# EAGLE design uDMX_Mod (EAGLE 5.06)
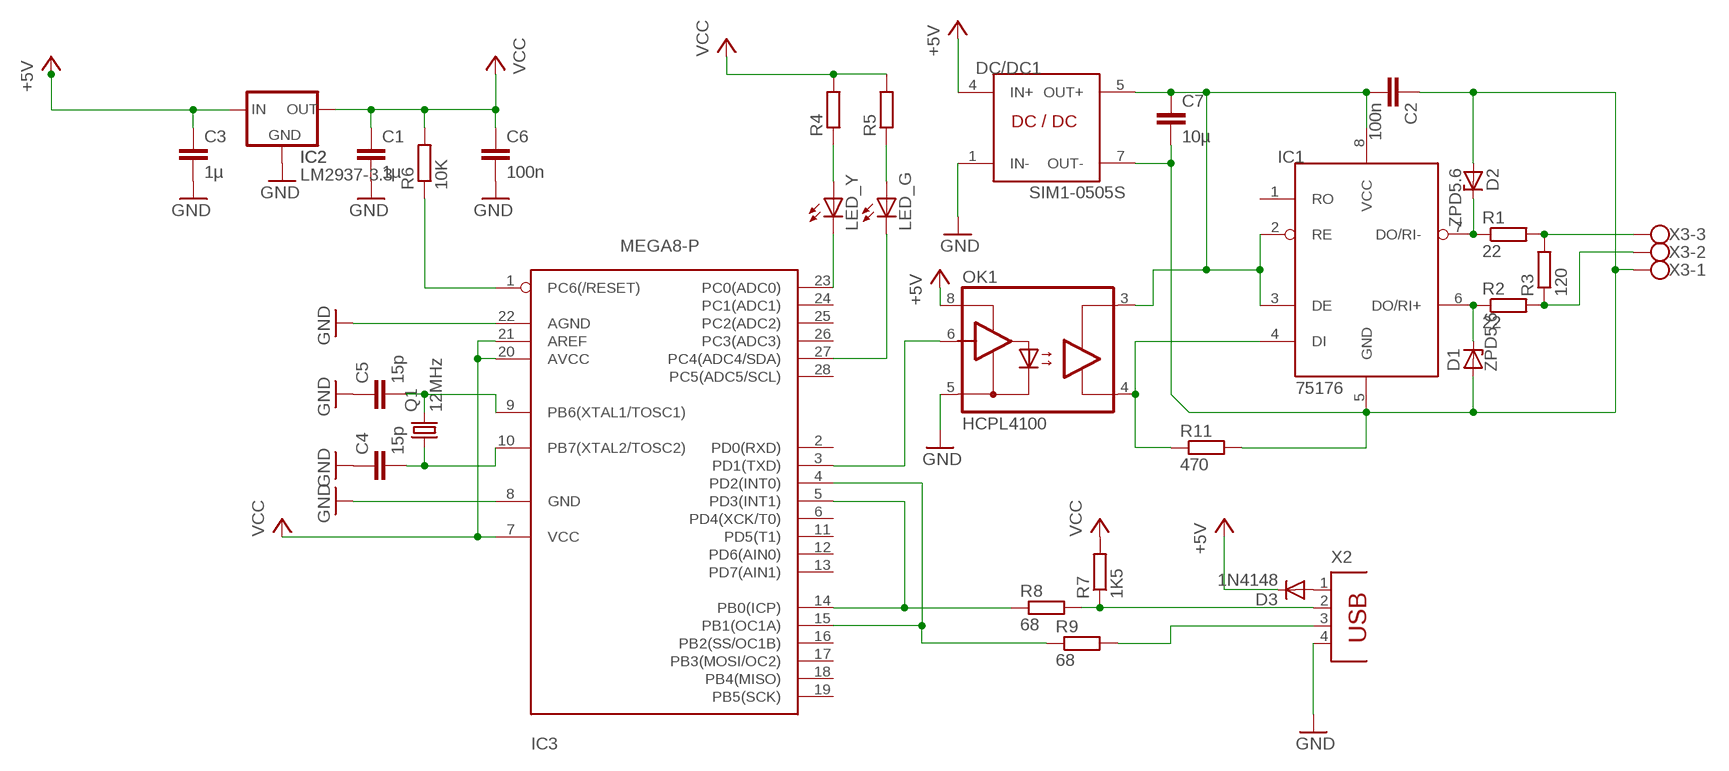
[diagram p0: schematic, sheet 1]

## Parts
C1  1µ  C2.5/4  [C2.5-4]
C2  100n  C2.5/4  [C2.5-4]
C3  1µ  C2.5/4  [C2.5-4]
C4  15p  C2.5/4  [C2.5-4]
C5  15p  C2.5/4  [C2.5-4]
C6  100n  C2.5/4  [C2.5-4]
C7  10µ  C2.5/4  [C2.5-4]
D1  ZPD5.6  ZPD  [DO35Z10]
D2  ZPD5.6  ZPD  [DO35Z10]
D3  1N4148  [DO35-10]
DC/DC1  SIM1-0505S  [DIL08]
IC1  75176  [DIL08]
IC2  LM2937-3.3  LM2937  [TO220S]
IC3  MEGA8-P  [DIL28-3]
LED_G  LED3MM  [LED3MM]
LED_Y  LED3MM  [LED3MM]
OK1  HCPL4100  [DIL08]
Q1  12MHz  CRYSTALHC18U-V  [HC18U-V]
R1  22  R-EU_0204/7  [0204/7]
R2  22  R-EU_0204/7  [0204/7]
R3  120  R-EU_0204/7  [0204/7]
R4  R-EU_0204/7  [0204/7]
R5  R-EU_0204/7  [0204/7]
R6  10K  R-EU_0204/7  [0204/7]
R7  1K5  R-EU_0204/7  [0204/7]
R8  68  R-EU_0204/7  [0204/7]
R9  68  R-EU_0204/7  [0204/7]
R11  470  R-EU_0204/7  [0204/7]
X2  PN61729  [PN61729]
X3  W237-103  [W237-103]

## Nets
+5V: C3.1 D3.C DC/DC1.4(IN+) IC2.1(IN) OK1.8(VDD1)
D-: R7.1 R8.2 X2.2
DMX2: R1.2 R3.2 X3.3
GND: C1.2 C3.2 C4.1 C5.1 C6.2 DC/DC1.1(IN-) IC2.2(GND) IC3.8(GND) IC3.22(AGND) OK1.5(GND1) X2.4
N$1: IC3.5(PD3(INT1)) IC3.14(PB0(ICP)) R8.1
N$3: D2.C IC1.7(DO/RI-) R1.1
N$4: D1.C IC1.6(DO/RI+) R2.1
N$5: IC3.3(PD1(TXD)) OK1.6(VI)
N$6: IC3.4(PD2(INT0)) IC3.15(PB1(OC1A)) R9.1
N$7: LED_Y.A R4.1
N$8: LED_G.A R5.1
N$9: IC3.23(PC0(ADC0)) LED_Y.K(C)
N$10: R9.2 X2.3
N$11: IC3.27(PC4(ADC4/SDA)) LED_G.K(C)
N$12: C2.1 C7.2 D1.A D2.A DC/DC1.7(OUT-) IC1.5(GND) R11.2 X3.1
N$13: R2.2 R3.1 X3.2
N$14: D3.A X2.1
N$15: C2.2 C7.1 DC/DC1.5(OUT+) IC1.2(RE) IC1.3(DE) IC1.8(VCC) OK1.3(I+)
N$17: IC1.4(DI) OK1.4(I-) R11.1
N$37: C4.2 IC3.10(PB7(XTAL2/TOSC2)) Q1.1
N$38: C5.2 IC3.9(PB6(XTAL1/TOSC1)) Q1.2
N$47: IC3.1(PC6(/RESET)) R6.1
VCC: C1.1 C6.1 IC2.3(OUT) IC3.7(VCC) IC3.20(AVCC) IC3.21(AREF) R4.2 R5.2 R6.2 R7.2
Unconnected: IC1.1(RO) IC3.2(PD0(RXD)) IC3.6(PD4(XCK/T0)) IC3.11(PD5(T1)) IC3.12(PD6(AIN0)) IC3.13(PD7(AIN1)) IC3.16(PB2(SS/OC1B)) IC3.17(PB3(MOSI/OC2)) IC3.18(PB4(MISO)) IC3.19(PB5(SCK)) IC3.24(PC1(ADC1)) IC3.25(PC2(ADC2)) IC3.26(PC3(ADC3)) IC3.28(PC5(ADC5/SCL))

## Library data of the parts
C1-C7 = capacitor-wima:C: CAPACITOR
D1 D2 = diode:ZPD: Z DIODE
D3 = diode:1N4148: DIODE
DC/DC1 = Lutz:SIM1-0505S
IC1 = Lutz:75176
IC2 = Lutz:LM2937: VOLTAGE REGULATOR
IC3 = atmel:MEGA8-P: MICROCONTROLLER 8 Kbytes FLASH 1 kbytes SRAM 512 bytes EEPROM USART 4-channel 10 bit ADC 2-channel 8 bit ADC Source: avr.lbr
LED_G LED_Y = led:LED: LED
OK1 = Lutz:HCPL4100: HEWLETT PACKARD OPTO COUPLER
Q1 = crystal:CRYSTAL: CRYSTAL
R1-R9 R11 = rcl:R-EU_: RESISTOR, European symbol
X2 = con-berg:PN61729: BERG USB connector
X3 = con-wago-500:W237-103: WAGO SCREW CLAMP

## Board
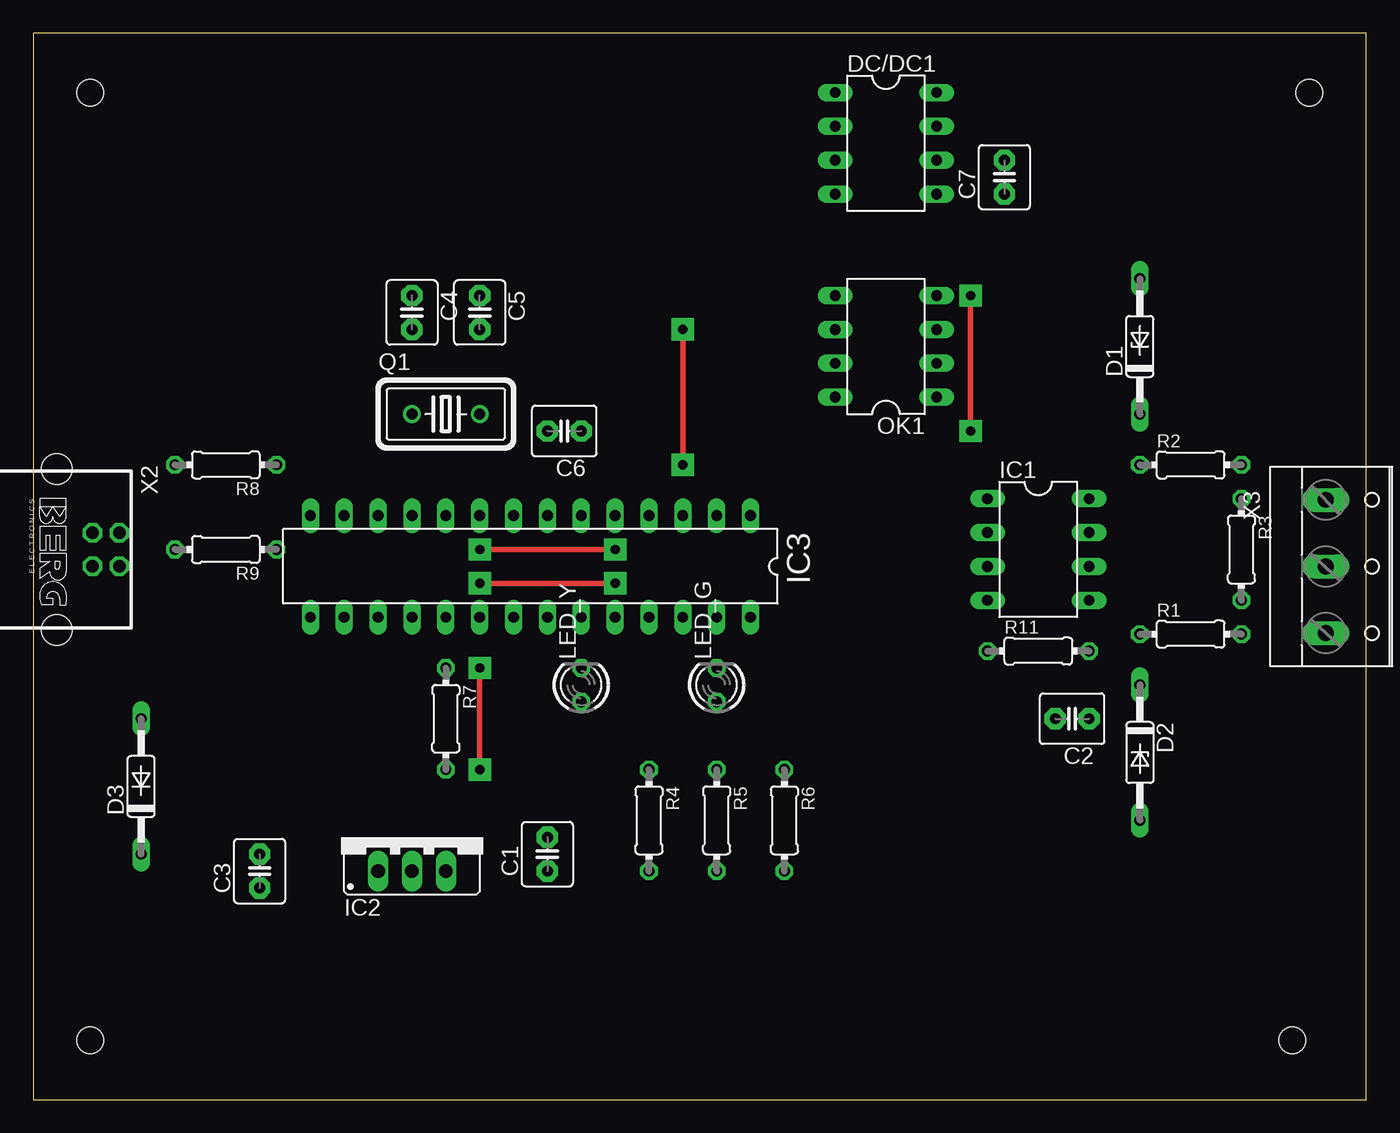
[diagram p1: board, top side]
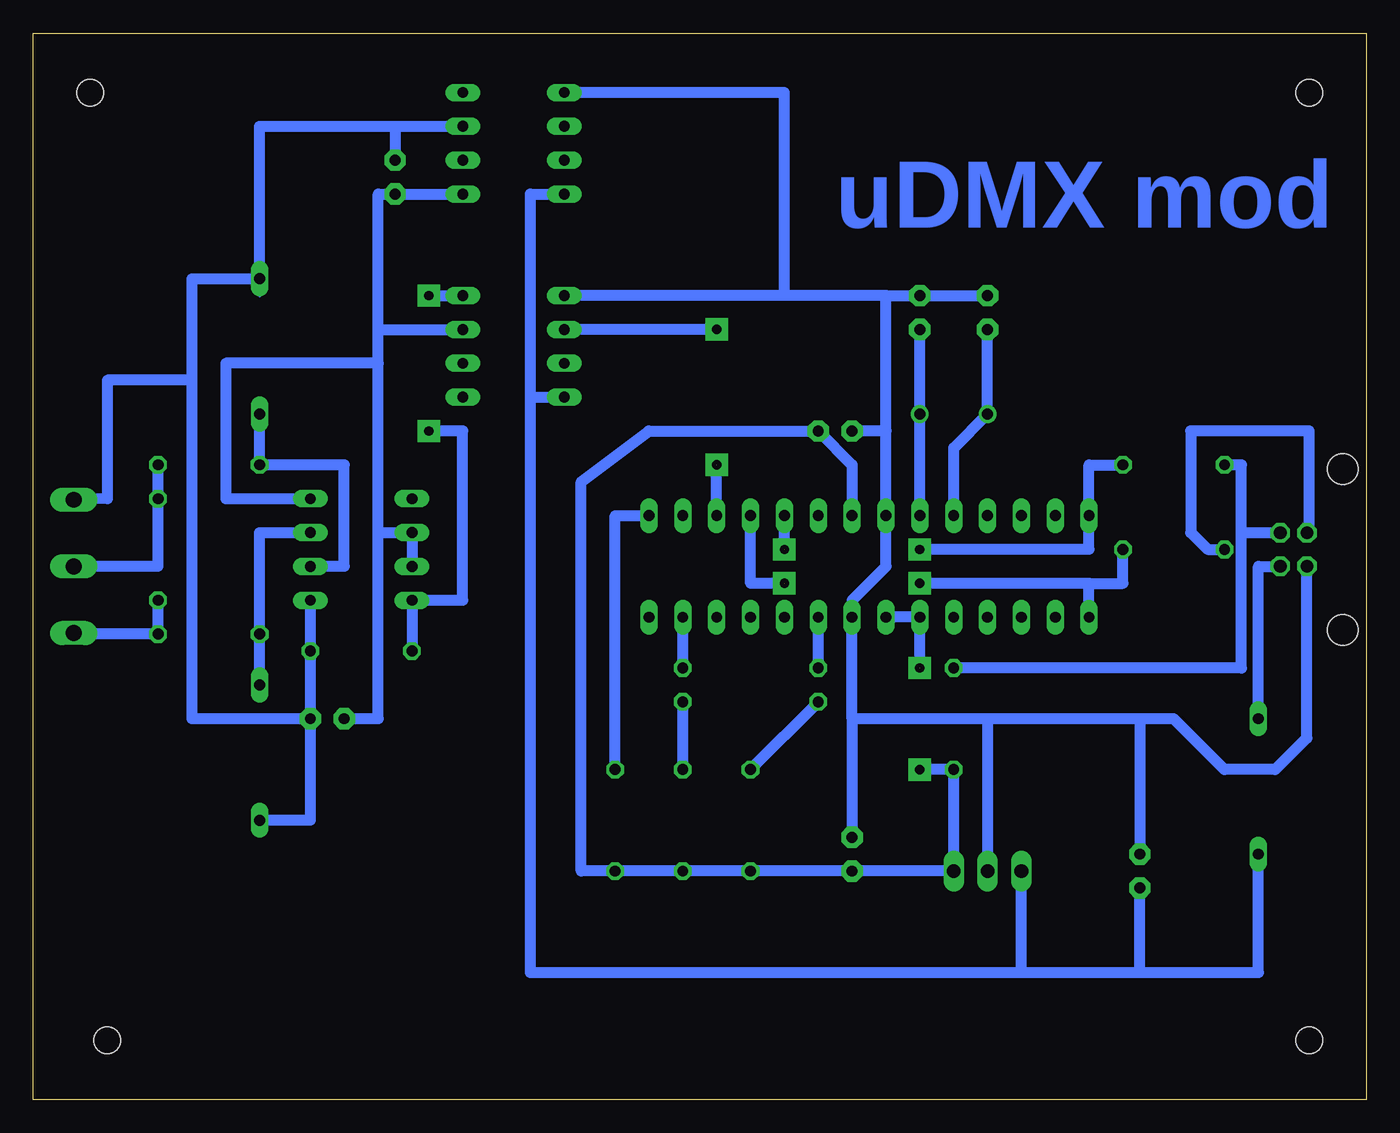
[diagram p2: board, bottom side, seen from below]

Size 100 x 80 mm. Coordinates in mm from the lower left corner, seen from the top.
Outline: 0,0 100,0 100,80 0,80 0,0
Copper layers (1*16): Top 0.035mm / dielectric 1.5mm / Bottom 0.035mm
Design rules "default": minimum track width 10mil, minimum drill 24mil, track to track 8mil, track to pad 8mil, pad to pad 8mil, via to via 8mil, smd to smd 8mil, copper to edge 40mil, drill to drill 8mil, minimum pad ring 10mil, minimum via ring 8mil, stop-mask expansion 4mil, vias tented up to drill 0mil, thermal gap 10mil
Holes 2 mm at 4.28,4.44 94.45,4.44 95.72,75.56 4.28,75.56

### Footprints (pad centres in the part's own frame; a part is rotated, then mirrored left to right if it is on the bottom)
C2.5-4 = drill 0.813 pad 1.6 octagon: 1 -1.27,0; 2 1.27,0
DO35Z10 = drill 0.813 long: A 5.08,0; C -5.08,0
DO35-10 = drill 0.813 long: A 5.08,0; C -5.08,0
DIL08 = drill 0.813 long: 1 -3.81,-3.81; 2 -1.27,-3.81; 3 1.27,-3.81; 4 3.81,-3.81; 5 3.81,3.81; 6 1.27,3.81; 7 -1.27,3.81; 8 -3.81,3.81
TO220S = drill 1.016 long: 1 -2.54,-2.54; 2 0,-2.54; 3 2.54,-2.54
DIL28-3 = drill 0.813 long: 1 -16.51,-3.81; 2 -13.97,-3.81; 3 -11.43,-3.81; 4 -8.89,-3.81; 5 -6.35,-3.81; 6 -3.81,-3.81; 7 -1.27,-3.81; 8 1.27,-3.81; 9 3.81,-3.81; 10 6.35,-3.81; 11 8.89,-3.81; 12 11.43,-3.81; 13 13.97,-3.81; 14 16.51,-3.81; 15 16.51,3.81; 16 13.97,3.81; 17 11.43,3.81; 18 8.89,3.81; 19 6.35,3.81; 20 3.81,3.81; 21 1.27,3.81; 22 -1.27,3.81; 23 -3.81,3.81; 24 -6.35,3.81; 25 -8.89,3.81; 26 -11.43,3.81; 27 -13.97,3.81; 28 -16.51,3.81
LED3MM = drill 0.813 octagon: A -1.27,0; K 1.27,0
HC18U-V = drill 0.813 round: 1 -2.54,0; 2 2.54,0
0204/7 = drill 0.813 octagon: 1 -3.81,0; 2 3.81,0
PN61729 = drill 0.95 octagon: 1 1.25,4.71; 2 -1.25,4.71; 3 -1.25,2.71; 4 1.25,2.71 | hole 2.3: -6.02,0; 6.02,0
W237-103 = drill 1.194 long: 1 -5,-1.29; 2 0,-1.29; 3 5,-1.29

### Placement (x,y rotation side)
C1  38.57,18.41 90 top
C2  77.94,28.57 180 top
C3  16.98,17.14 90 top
C4  28.41,59.05 270 top
C5  33.49,59.05 270 top
C6  39.84,50.16 180 top
C7  72.86,69.21 90 top
D1  83.02,56.51 90 top
D2  83.02,26.03 270 top
D3  8.09,23.49 90 top
DC/DC1  63.97,71.75 270 top
IC1  75.4,41.27 270 top
IC2  28.41,19.68 0 top
IC3  37.3,40 180 top
LED_G  51.27,31.11 90 top
LED_Y  41.11,31.11 90 top
OK1  63.97,56.51 90 top
Q1  30.95,51.43 0 top
R1  86.83,34.92 0 top
R2  86.83,47.62 0 top
R3  90.64,41.27 270 top
R4  46.19,20.95 270 top
R5  51.27,20.95 270 top
R6  56.35,20.95 270 top
R7  30.95,28.57 270 top
R8  14.44,47.62 180 top
R9  14.44,41.27 180 top
R11  75.4,33.65 0 top
X2  1.74,41.27 270 top
X3  98.26,40 270 top

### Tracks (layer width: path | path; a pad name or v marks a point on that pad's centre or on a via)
+5V
  Bottom 0.254: 8.09,9.52 16.98,9.52 25.87,9.52 62.7,9.52
  Bottom 0.813: 62.7,52.7 62.7,67.94 DC/DC1.4 | D3.C 8.09,9.52 62.7,9.52 62.7,52.7 | 25.87,9.52 IC2.1 | 16.98,9.52 C3.1 | 62.7,52.7 OK1.8
D-
  Bottom 0.254: 6.82,42.54 X2.2
  Bottom 0.813: R7.1 9.36,32.38 9.36,42.54 | 9.36,42.54 6.82,42.54 | R8.2 9.36,47.62 9.36,42.54
DMX2
  Bottom 0.406: 96.99,34.92 X3.3
  Bottom 0.813: R3.2 R1.2 96.99,34.92
GND
  Bottom 0.254: 36.03,40 IC3.8 | 36.03,60.32 C5.1 C4.1 | 19.52,28.57 28.41,28.57
  Bottom 0.406: IC3.8 36.03,50.16 36.03,60.32 | 16.98,28.57 19.52,28.57 | 38.57,28.57 28.41,28.57 | IC3.22 38.57,37.46
  Bottom 0.813: 43.65,60.32 43.65,75.56 DC/DC1.1 | X2.4 4.45,27.13 6.82,24.76 10.63,24.76 14.44,28.57 16.98,28.57 | 36.03,60.32 C4.1 | 38.57,28.57 C1.2 | 36.03,50.16 C6.2 | 28.41,28.57 IC2.2 | 16.98,28.57 C3.2 | 16.98,28.57 38.57,28.57 | 38.57,28.57 IC3.22 | 38.57,37.46 36.03,40 36.03,60.32 | 36.03,60.32 43.65,60.32 | 43.65,60.32 OK1.5
N$1  (via drill 0.7 pad 1.68)  (1 unrouted)
  Top 0.406: v33.49,41.27 43.65,41.27
  Bottom 0.813: R8.1 20.79,47.62 IC3.14 20.79,41.27 v33.49,41.27 | 43.65,41.27 IC3.5
N$2  (via drill 0.7 pad 1.68)
  other vias: 48.73,47.62
N$3
  Bottom 0.813: IC1.7 83.02,42.54 R1.1 D2.C
N$4
  Bottom 0.813: IC1.6 76.67,40 76.67,47.62 R2.1 D1.C
N$5  (via drill 0.7 pad 1.68)  (1 unrouted)
  Top 0.406: 48.73,47.62 v48.73,57.78
  Bottom 0.813: v48.73,57.78 OK1.6 | IC3.3 48.73,47.62
N$6  (via drill 0.6)  (1 unrouted)
  Top 0.406: v33.49,38.73 43.65,38.73
  Bottom 0.813: R9.1 18.25,38.73 20.79,38.73 | IC3.15 20.79,38.73 | 20.79,38.73 v33.49,38.73 | IC3.4 46.19,38.73 43.65,38.73
N$7
  Bottom 0.813: R4.1 LED_Y.A
N$8
  Bottom 0.813: R5.1 LED_G.A
N$9
  Bottom 0.813: LED_Y.K IC3.23
N$10
  Bottom 0.406: 4.28,42.54 4.3,42.52 X2.3
  Bottom 0.813: R9.2 11.9,41.27 13.17,42.54 13.17,50.16 4.28,50.16 4.28,42.54
N$11
  Bottom 0.813: LED_G.K IC3.27
N$12
  Bottom 0.254: 83.02,62.86 D1.A 83.02,60.32 | C2.1 R11.2 C2.1
  Bottom 0.813: D2.A 79.21,20.95 C2.1 | C2.1 IC1.5 | 72.86,73.02 83.02,73.02 D1.A 88.1,61.59 88.1,53.97 | 72.86,73.02 DC/DC1.7 | 72.86,73.02 C7.2 | C2.1 88.1,28.57 88.1,53.97 | 88.1,53.97 94.45,53.97 94.45,45.08 X3.1
N$13
  Bottom 0.254: R3.1 R2.2
  Bottom 0.406: 90.64,41.27 R3.1 R2.2
  Bottom 0.813: X3.2 90.64,40 90.64,41.27 R2.2
N$14
  Bottom 0.254: 6.82,40 X2.1
  Bottom 0.813: 6.82,40 8.09,40 D3.A
N$15
  Bottom 0.254: IC1.2 IC1.3
  Bottom 0.406: 74.13,67.94 C7.1
  Bottom 0.813: C2.2 74.13,28.57 74.13,42.54 | IC1.3 IC1.2 74.13,42.54 | 74.13,55.24 85.56,55.24 85.56,45.08 IC1.8 | 74.13,55.24 74.13,57.78 | 74.13,57.78 74.13,67.94 DC/DC1.5 | 74.13,42.54 74.13,55.24 | 74.13,57.78 OK1.3
N$16  (via drill 0.7 pad 1.68)
  other vias: 43.65,41.27
N$17  (via drill 0.7 pad 1.68)
  Top 0.406: v70.32,50.16 v70.32,60.32
  Bottom 0.813: R11.1 IC1.4 67.78,37.46 67.78,50.16 v70.32,50.16 | v70.32,60.32 OK1.4
N$18  (via drill 0.7 pad 1.68)
  other vias: 33.49,38.73
N$19  (via drill 0.7 pad 1.68)
  other vias: 43.65,38.73
N$21  (via drill 0.7 pad 1.68)
  other vias: 33.49,32.38
N$22  (via drill 0.7 pad 1.68)
  other vias: 33.49,24.76
N$37
  Bottom 0.813: C4.2 Q1.1 30.95,48.89 IC3.10
N$38
  Bottom 0.813: C5.2 Q1.2 IC3.9
N$47
  Bottom 0.813: R6.1 56.35,43.81 IC3.1
VCC  (via drill 0.6)  (1 unrouted)
  Top 0.406: v33.49,24.76 33.49,32.38
  Bottom 0.406: IC3.20 IC3.21
  Bottom 0.813: IC3.7 38.57,47.62 C6.1 53.81,50.16 58.89,46.35 58.89,17.14 R6.2 R5.2 R4.2 C1.1 IC2.3 R7.2 v33.49,24.76 | IC3.21 IC3.20 33.49,32.38

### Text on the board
Bottom: uDMX mod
